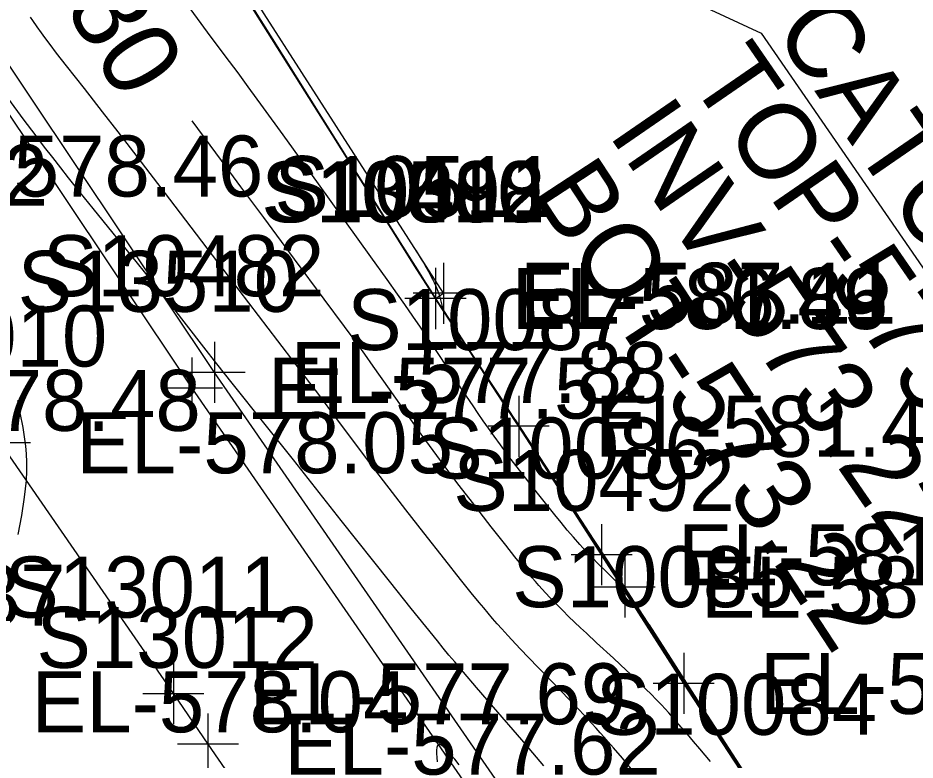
# Model space of a CAD drawing. Extents: x 1729869 to 1735532, y 648588 to 653771.
# Drawn here: x 1731975.7 to 1732034.5, y 650943.7 to 650992.4 of the extents above; entities that cross this region are included whole.
import ezdxf

# ---------------------------------------------------------------- set-up
doc = ezdxf.new("R2010")
doc.units = 0
for name, color, linetype in [('SURVEY - CONTOURS - Index with Text', 7, 'Continuous'), ('SURVEY - CONTOURS - Intermediate with optional Text', 7, 'Continuous'), ('SURVEY - DRAINAGE - Storm Sewer Text', 7, 'Continuous'), ('SURVEY - DTM - Breaklines', 7, 'Continuous'), ('SURVEY - DTM - Breaklines - Points - Elevations', 7, 'Continuous'), ('SURVEY - DTM - Breaklines - Points - Locators', 7, 'Continuous'), ('SURVEY - DTM - Breaklines - Points - Numbers', 7, 'Continuous'), ('SURVEY - MISCELLANEOUS - Bottom of MH and CB', 7, 'Continuous'), ('SURVEY - ROADSIDE BARRIERS - Points - Elevations', 7, 'Continuous'), ('SURVEY - ROADSIDE BARRIERS - Points - Locators', 7, 'Continuous'), ('SURVEY - ROADSIDE BARRIERS - Points - Numbers', 7, 'Continuous'), ('SURVEY - ROADSIDE BARRIERS with Text', 7, 'Continuous'), ('SURVEY - TRAFFIC CONTROL - Pavement Marking - Points - Elevations', 7, 'Continuous'), ('SURVEY - TRAFFIC CONTROL - Pavement Marking - Points - Numbers', 7, 'Continuous'), ('SURVEY - TRANSPORTATION - Features', 7, 'Continuous'), ('SURVEY - TRANSPORTATION - Features - Points - Elevations', 7, 'Continuous'), ('SURVEY - TRANSPORTATION - Features - Points - Locators', 7, 'Continuous'), ('SURVEY - TRANSPORTATION - Features - Points - Numbers', 7, 'Continuous'), ('SURVEY - TRANSPORTATION - Roads', 7, 'Continuous'), ('SURVEY - TRANSPORTATION - Roads - Points - Elevations', 7, 'Continuous'), ('SURVEY - TRANSPORTATION - Roads - Points - Locators', 7, 'Continuous'), ('SURVEY - TRANSPORTATION - Roads - Points - Numbers', 7, 'Continuous')]:
    doc.layers.add(name, color=color, linetype=linetype)

msp = doc.modelspace()

# ---------------------------------------------------------------- linework, layer by layer
at = {"layer": 'SURVEY - CONTOURS - Index with Text'}
for points in [[(1731990.106, 650994.569), (1731998.513, 650981.186), (1732002.185, 650975.342), (1732002.741, 650974.46), (1732003.04, 650973.985), (1732003.674, 650973.013), (1732005.357, 650970.432), (1732008.528, 650965.586), (1732010.41, 650962.695), (1732013.748, 650957.558), (1732014.896, 650955.782), (1732016.272, 650953.637), (1732017.448, 650951.8)], [(1732021.076, 650943.613), (1732020.374, 650944.448), (1732019.972, 650944.923), (1732019.566, 650945.397), (1732019.158, 650945.869), (1732018.749, 650946.335), (1732018.339, 650946.792), (1732017.857, 650947.317), (1732017.521, 650947.672), (1732017.183, 650948.02), (1732016.841, 650948.364), (1732016.425, 650948.772), (1732016.001, 650949.177), (1732015.574, 650949.58), (1732014.714, 650950.376), (1732013.615, 650951.392), (1732012.947, 650952.015), (1732012.555, 650952.384), (1732012.163, 650952.755), (1732011.775, 650953.128), (1732011.393, 650953.502), (1732011.018, 650953.877), (1732010.572, 650954.337), (1732010.264, 650954.668), (1732010.039, 650954.914), (1732009.819, 650955.161), (1732009.601, 650955.41), (1732009.385, 650955.661), (1732009.171, 650955.915), (1732008.865, 650956.283), (1732008.56, 650956.657), (1732008.257, 650957.034), (1732007.654, 650957.794), (1732006.706, 650959.006), (1732005.478, 650960.585), (1732004.613, 650961.706), (1732003.988, 650962.526), (1732003.559, 650963.098), (1732003.133, 650963.672), (1732002.655, 650964.329), (1732002.122, 650965.074), (1732000.037, 650968.023), (1731998.972, 650969.535), (1731998.416, 650970.316), (1731997.976, 650970.923), (1731997.093, 650972.126), (1731995.758, 650973.935), (1731993.813, 650976.554), (1731991.792, 650979.287), (1731990.304, 650981.299), (1731989.037, 650983.012), (1731987.096, 650985.62)], [(1732017.052, 650952.571), (1732020.203, 650947.655), (1732023.156, 650943.062)]]:
    msp.add_lwpolyline(points, dxfattribs=at)
at = {"layer": 'SURVEY - CONTOURS - Intermediate with optional Text'}
for points in [[(1731989.084, 650996.186), (1731998.643, 650980.975), (1732002.18, 650975.348), (1732002.821, 650974.33), (1732003.042, 650973.979), (1732003.573, 650973.166), (1732005.618, 650970.028), (1732008.097, 650966.237), (1732009.68, 650963.806), (1732013.378, 650958.105), (1732014.575, 650956.253), (1732015.794, 650954.353), (1732018.615, 650949.944), (1732019.823, 650948.068), (1732021.324, 650945.754), (1732025.088, 650939.975)], [(1732024.432, 650940.948), (1732021.077, 650946.081), (1732019.818, 650948.016), (1732019.004, 650949.276), (1732017.755, 650951.222), (1732014.969, 650955.582), (1732013.54, 650957.806), (1732011.123, 650961.548), (1732008.758, 650965.2), (1732007.097, 650967.75), (1732004.464, 650971.784), (1732003.509, 650973.256), (1732003.143, 650973.819), (1732003.047, 650973.966), (1732002.653, 650974.591), (1732001.84, 650975.875), (1732000.154, 650978.558), (1731996.288, 650984.713), (1731989.383, 650995.69)], [(1731990.681, 650993.634), (1731998.408, 650981.344), (1732002.414, 650974.971), (1732002.903, 650974.198), (1732003.045, 650973.971), (1732003.478, 650973.309), (1732003.897, 650972.662), (1732005.79, 650969.759), (1732008.134, 650966.17), (1732009.607, 650963.904), (1732013.159, 650958.421), (1732014.461, 650956.401), (1732015.852, 650954.231), (1732018.371, 650950.292), (1732019.449, 650948.616), (1732020.487, 650947.013), (1732023.192, 650942.863)], [(1732023.075, 650942.993), (1732021.446, 650945.479), (1732020.718, 650946.598), (1732020.355, 650947.16), (1732019.601, 650948.335), (1732019.313, 650948.782), (1732015.654, 650954.504), (1732015.45, 650954.799), (1732015.181, 650955.106), (1732014.899, 650955.407), (1732014.605, 650955.704), (1732014.304, 650956.001), (1732013.657, 650956.635), (1732013.4, 650956.894), (1732013.108, 650957.196), (1732012.913, 650957.403), (1732012.508, 650957.846), (1732012.1, 650958.309), (1732011.691, 650958.787), (1732011.281, 650959.277), (1732010.873, 650959.775), (1732010.344, 650960.431), (1732009.729, 650961.203), (1732009.336, 650961.703), (1732008.944, 650962.204), (1732008.555, 650962.706), (1732008.173, 650963.207), (1732007.798, 650963.703), (1732007.303, 650964.371), (1732006.895, 650964.933), (1732006.52, 650965.461), (1732006.184, 650965.941), (1732005.85, 650966.429), (1732005.516, 650966.92), (1732004.85, 650967.913), (1732003.091, 650970.556), (1732002.406, 650971.579), (1732002.063, 650972.086), (1732001.563, 650972.817), (1732001.041, 650973.567), (1732000.568, 650974.242), (1731999.875, 650975.219), (1731998.808, 650976.708), (1731995.375, 650981.484), (1731993.064, 650984.699), (1731991.789, 650986.463), (1731990.784, 650987.843), (1731990.114, 650988.754), (1731989.278, 650989.879), (1731988.115, 650991.435), (1731987.462, 650992.318), (1731986.977, 650992.985)], [(1731990.855, 650993.383), (1731992.233, 650991.196), (1731999.955, 650978.894), (1732001.982, 650975.668), (1732002.306, 650975.156), (1732003.039, 650973.988), (1732003.615, 650973.109), (1732005.261, 650970.585), (1732008.841, 650965.116), (1732011.841, 650960.514), (1732014.23, 650956.84), (1732015.338, 650955.125), (1732016.869, 650952.735), (1732019.022, 650949.373), (1732020.391, 650947.248), (1732023.069, 650943.115)], [(1732015.88, 650943.139), (1732015.303, 650943.821), (1732014.723, 650944.499), (1732014.379, 650944.895), (1732014.113, 650945.198), (1732013.846, 650945.499), (1732013.578, 650945.799), (1732013.308, 650946.096), (1732013.035, 650946.392), (1732012.761, 650946.686), (1732012.463, 650947.001), (1732011.861, 650947.625), (1732010.649, 650948.87), (1732009.749, 650949.805), (1732008.603, 650951.001), (1732008.057, 650951.579), (1732007.786, 650951.871), (1732007.397, 650952.3), (1732007.096, 650952.639), (1732006.799, 650952.982), (1732006.503, 650953.328), (1732006.21, 650953.677), (1732005.92, 650954.028), (1732005.397, 650954.67), (1732004.7, 650955.54), (1732003.659, 650956.856), (1732002.291, 650958.596), (1732001.105, 650960.115), (1732000.226, 650961.25), (1731999.64, 650962.015), (1731999.139, 650962.677), (1731996.633, 650966.023), (1731995.338, 650967.757), (1731994.821, 650968.441), (1731993.918, 650969.621), (1731992.721, 650971.184), (1731990.186, 650974.504), (1731987.737, 650977.723), (1731985.645, 650980.472), (1731983.283, 650983.558), (1731982.247, 650984.901), (1731981.239, 650986.198), (1731980.04, 650987.728), (1731978.87, 650989.214), (1731978.542, 650989.635), (1731978.219, 650990.053), (1731977.788, 650990.619), (1731977.45, 650991.075), (1731977.227, 650991.382), (1731976.94, 650991.784), (1731976.652, 650992.2), (1731976.507, 650992.415)], [(1732010.162, 650943.333), (1732009.442, 650944.182), (1732008.719, 650945.024), (1732006.847, 650947.179), (1732005.737, 650948.467), (1732004.879, 650949.469), (1732004.31, 650950.142), (1732003.934, 650950.592), (1732003.555, 650951.051), (1732003.174, 650951.517), (1732002.413, 650952.456), (1732001.457, 650953.648), (1732000.028, 650955.442), (1731996.874, 650959.422), (1731993.744, 650963.381), (1731991.892, 650965.712), (1731989.735, 650968.417), (1731988.731, 650969.688), (1731987.879, 650970.775), (1731985.742, 650973.515), (1731985.019, 650974.433), (1731984.439, 650975.159), (1731983.531, 650976.284), (1731980.611, 650979.877), (1731979.774, 650980.914), (1731979.007, 650981.874), (1731978.49, 650982.529), (1731977.966, 650983.203), (1731977.43, 650983.899), (1731976.811, 650984.717), (1731976.104, 650985.664), (1731975.032, 650987.116)], [(1732001.792, 650977.102), (1732002.119, 650976.553), (1732002.278, 650976.281), (1732002.434, 650976.011), (1732002.584, 650975.744), (1732002.728, 650975.481), (1732002.852, 650975.245), (1732002.967, 650975.012), (1732003.074, 650974.785), (1732003.168, 650974.564), (1732003.251, 650974.349), (1732003.319, 650974.141), (1732003.565, 650973.186), (1732005.852, 650969.689), (1732007.264, 650967.532), (1732008.58, 650965.518), (1732009.766, 650963.72), (1732011.373, 650961.259), (1732014.557, 650956.362), (1732015.655, 650954.661), (1732017.373, 650951.978), (1732019.237, 650949.069), (1732020.654, 650946.868), (1732023.327, 650942.738)], [(1731975.648, 650967.271), (1731975.883, 650966.139), (1731975.943, 650965.833), (1731976.002, 650965.52), (1731976.057, 650965.2), (1731976.126, 650964.75), (1731976.184, 650964.277), (1731976.227, 650963.774), (1731976.25, 650963.237), (1731976.249, 650962.662), (1731976.218, 650962.041), (1731976.102, 650960.937), (1731975.915, 650959.739), (1731975.676, 650958.485)], [(1732008.27, 650966.009), (1732012.614, 650959.368), (1732014.354, 650956.7), (1732015.366, 650955.139), (1732016.393, 650953.542), (1732019.226, 650949.118), (1732020.876, 650946.552), (1732023.542, 650942.425)], [(1732012.975, 650958.833), (1732014.743, 650956.125), (1732015.752, 650954.569), (1732016.964, 650952.684), (1732019.526, 650948.681), (1732021.348, 650945.847), (1732024.638, 650940.745)], [(1732020.428, 650947.332), (1732024.562, 650940.894)], [(1732004.606, 650943.398), (1732004.311, 650943.762), (1732004.067, 650944.054), (1732003.915, 650944.228), (1732003.843, 650944.308), (1732003.709, 650944.449), (1732003.586, 650944.566), (1732003.475, 650944.656), (1732003.378, 650944.714), (1732003.296, 650944.738), (1732003.23, 650944.722), (1732003.175, 650944.65), (1732003.141, 650944.524), (1732003.126, 650944.349), (1732003.128, 650944.13), (1732003.143, 650943.873), (1732003.17, 650943.584)]]:
    msp.add_lwpolyline(points, dxfattribs=at)
at = {"layer": 'SURVEY - DRAINAGE - Storm Sewer Text'}
msp.add_lwpolyline([(1731974.582, 651014.491), (1732024.407, 650991.366), (1732055.922, 650945.63)], dxfattribs=at)
at = {"layer": 'SURVEY - DTM - Breaklines'}
for points in [[(1732003.052, 650973.968), (1732003.581, 650974.31), (1731989.555, 650996.2), (1731978.607, 651014.105), (1731965.163, 651035.183), (1731951.942, 651056.407), (1731938.343, 651077.385), (1731924.593, 651098.267), (1731910.737, 651119.08), (1731897.035, 651139.992), (1731883.266, 651160.86), (1731869.448, 651181.699), (1731855.766, 651202.623), (1731841.938, 651223.455), (1731828.188, 651244.335), (1731813.142, 651266.45), (1731799.479, 651287.546), (1731797.002, 651291.324), (1731796.491, 651290.994), (1731796.236, 651290.836)], [(1732113.007, 650812.16), (1732098.885, 650832.683), (1732084.634, 650853.212), (1732070.443, 650873.845), (1732055.723, 650894.054), (1732042.075, 650914.908), (1732029.016, 650934.005), (1732015.459, 650955.044), (1732003.052, 650973.968), (1731989.798, 650995.07), (1731976.605, 651016.091), (1731963.895, 651036.118), (1731950.601, 651057.29), (1731936.956, 651078.167), (1731923.152, 651099.071)], [(1732102.153, 650804.616), (1732073.748, 650845.695), (1732045.347, 650886.865), (1732016.99, 650927.983), (1731988.568, 650969.12), (1731970.42, 650996.284), (1731969.494, 650997.549)], [(1732112.277, 650811.653), (1732107.544, 650817.969), (1732106.693, 650820.85), (1732101.431, 650827.09), (1732092.964, 650839.561), (1732080.137, 650858.446), (1732079.028, 650860.985), (1732076.136, 650864.318), (1732073.466, 650867.37), (1732053.717, 650896.357), (1732047.019, 650907.102), (1732041.081, 650915.154), (1732035.472, 650923.431), (1732030.287, 650932), (1732024.797, 650940.36), (1732019.321, 650948.729), (1732013.942, 650957.165), (1732008.505, 650965.587), (1732003.045, 650973.966)]]:
    msp.add_lwpolyline(points, dxfattribs=at)
at = {"layer": 'SURVEY - DTM - Breaklines - Points - Locators'}
for p, q in [((1732003.045, 650975.966), (1732003.045, 650971.966)), ((1732003.052, 650975.968), (1732003.052, 650971.968)), ((1732003.052, 650975.968), (1732003.052, 650971.968)), ((1732003.581, 650976.31), (1732003.581, 650972.31)), ((1732005.581, 650974.31), (1732001.581, 650974.31)), ((1732005.045, 650973.966), (1732001.045, 650973.966)), ((1732005.052, 650973.968), (1732001.052, 650973.968)), ((1732005.052, 650973.968), (1732001.052, 650973.968)), ((1731988.568, 650971.12), (1731988.568, 650967.12)), ((1731990.568, 650969.12), (1731986.568, 650969.12)), ((1732008.505, 650967.587), (1732008.505, 650963.587)), ((1732010.505, 650965.587), (1732006.505, 650965.587)), ((1732013.942, 650959.165), (1732013.942, 650955.165)), ((1732015.942, 650957.165), (1732011.942, 650957.165)), ((1732015.459, 650957.044), (1732015.459, 650953.044)), ((1732017.459, 650955.044), (1732013.459, 650955.044)), ((1732019.321, 650950.729), (1732019.321, 650946.729)), ((1732021.321, 650948.729), (1732017.321, 650948.729))]:
    msp.add_line(p, q, dxfattribs=at)
at = {"layer": 'SURVEY - ROADSIDE BARRIERS - Points - Locators'}
for p, q in [((1732003.045, 650975.966), (1732003.045, 650971.966)), ((1732003.045, 650975.966), (1732003.045, 650971.966)), ((1732005.045, 650973.966), (1732001.045, 650973.966)), ((1732005.045, 650973.966), (1732001.045, 650973.966))]:
    msp.add_line(p, q, dxfattribs=at)
at = {"layer": 'SURVEY - ROADSIDE BARRIERS with Text'}
msp.add_lwpolyline([(1732003.045, 650973.966), (1731988.236, 650997.512), (1731985.958, 651001.172), (1731980.623, 651009.635), (1731978.235, 651013.364), (1731975.843, 651017.144), (1731972.561, 651022.261), (1731967.185, 651030.692), (1731963.964, 651035.947), (1731958.619, 651044.399), (1731947.921, 651061.362), (1731942.452, 651069.66), (1731928.639, 651090.556), (1731914.818, 651111.43), (1731900.526, 651133.036), (1731886.679, 651153.809), (1731872.913, 651174.694), (1731859.053, 651195.599), (1731845.3, 651216.428), (1731831.509, 651237.32), (1731817.644, 651258.224), (1731811.485, 651267.57), (1731801.259, 651282.765), (1731796.236, 651290.836)], dxfattribs=at)
msp.add_lwpolyline([(1732003.045, 650973.966), (1731988.236, 650997.512), (1731985.958, 651001.172), (1731980.623, 651009.635), (1731978.235, 651013.364), (1731975.843, 651017.144), (1731972.561, 651022.261), (1731967.185, 651030.692), (1731963.964, 651035.947), (1731958.619, 651044.399), (1731947.921, 651061.362), (1731942.452, 651069.66), (1731928.639, 651090.556), (1731914.818, 651111.43), (1731900.526, 651133.036), (1731886.679, 651153.809), (1731872.913, 651174.694), (1731859.053, 651195.599), (1731845.3, 651216.428), (1731831.509, 651237.32), (1731817.644, 651258.224), (1731811.485, 651267.57), (1731801.259, 651282.765), (1731796.236, 651290.836)], dxfattribs=at)
at = {"layer": 'SURVEY - TRANSPORTATION - Features'}
msp.add_lwpolyline([(1731968.374, 650998.805), (1731968.232, 650997.903), (1731968.308, 650996.747), (1731968.923, 650995.273), (1731987.082, 650968.094), (1732015.503, 650926.959), (1732043.863, 650885.836), (1732072.262, 650844.669), (1732100.659, 650803.577)], dxfattribs=at)
at = {"layer": 'SURVEY - TRANSPORTATION - Features - Points - Locators'}
for p, q in [((1731987.082, 650970.094), (1731987.082, 650966.094)), ((1731989.082, 650968.094), (1731985.082, 650968.094))]:
    msp.add_line(p, q, dxfattribs=at)
at = {"layer": 'SURVEY - TRANSPORTATION - Roads'}
msp.add_lwpolyline([(1731866.856, 651135.373), (1731893.09, 651092.809), (1731909.859, 651065.556), (1731920.319, 651048.509), (1731940.263, 651016.166), (1731949.77, 651000.883), (1731962.084, 650982.655), (1731974.516, 650964.508), (1731985.875, 650948.049), (1731988.138, 650944.751), (1732026.696, 650888.752), (1732054.033, 650849.307), (1732065.396, 650832.853), (1732083.577, 650806.529), (1732093.848, 650791.753), (1732098.884, 650784.51)], dxfattribs=at)
at = {"layer": 'SURVEY - TRANSPORTATION - Roads - Points - Locators'}
for p, q in [((1731976.516, 650964.508), (1731972.516, 650964.508)), ((1731985.875, 650950.049), (1731985.875, 650946.049)), ((1731987.875, 650948.049), (1731983.875, 650948.049)), ((1731988.138, 650946.751), (1731988.138, 650942.751)), ((1731990.138, 650944.751), (1731986.138, 650944.751))]:
    msp.add_line(p, q, dxfattribs=at)

# ---------------------------------------------------------------- texts
at = {"layer": 'SURVEY - CONTOURS - Index with Text'}
msp.add_text('580', height=5, rotation=300.99513, dxfattribs=at).set_placement((1731976.765, 650996.353))
at = {"layer": 'SURVEY - DRAINAGE - Storm Sewer Text'}
for s, p in [('CATCH BASIN', (1732025.123, 650991.57)), ('TOP-575.76', (1732019.603, 650988.351)), ('INV-573.22', (1732014.324, 650984.759))]:
    msp.add_text(s, height=5, rotation=304.56994, dxfattribs=at).set_placement(p)
at = {"layer": 'SURVEY - DTM - Breaklines - Points - Elevations'}
for s, p in [('EL-581.46', (1732008.045, 650971.966)), ('EL-586.89', (1732008.052, 650971.968)), ('EL-586.89', (1732008.052, 650971.968)), ('EL-587.11', (1732008.581, 650972.31)), ('EL-577.88', (1731993.568, 650967.12)), ('EL-581.45', (1732013.505, 650963.587)), ('EL-581.21', (1732018.942, 650955.165)), ('EL-589.53', (1732020.459, 650953.044)), ('EL-580.47', (1732024.321, 650946.729))]:
    msp.add_text(s, height=4, dxfattribs=at).set_placement(p)
at = {"layer": 'SURVEY - DTM - Breaklines - Points - Numbers'}
for s, p in [('S10510', (1731991.639, 650978.968)), ('S10088', (1731991.758, 650978.966)), ('S10493', (1731991.812, 650978.968)), ('S10511', (1731992.499, 650979.31)), ('S10482', (1731977.328, 650974.12)), ('S10087', (1731997.265, 650970.587)), ('S10086', (1732002.592, 650962.165)), ('S10492', (1732004.219, 650960.044)), ('S10085', (1732008.081, 650953.729)), ('S10084', (1732013.557, 650945.36))]:
    msp.add_text(s, height=4, dxfattribs=at).set_placement(p)
at = {"layer": 'SURVEY - MISCELLANEOUS - Bottom of MH and CB'}
msp.add_text('BOT-573.22', height=5, rotation=303.22074, dxfattribs=at).set_placement((1732009.257, 650980.926))
at = {"layer": 'SURVEY - ROADSIDE BARRIERS - Points - Elevations'}
msp.add_text('EL-581.46', height=4, dxfattribs=at).set_placement((1732008.045, 650971.966))
msp.add_text('EL-581.46', height=4, dxfattribs=at).set_placement((1732008.045, 650971.966))
at = {"layer": 'SURVEY - ROADSIDE BARRIERS - Points - Numbers'}
msp.add_text('S13302', height=4, dxfattribs=at).set_placement((1731991.805, 650978.966))
msp.add_text('S13302', height=4, dxfattribs=at).set_placement((1731991.805, 650978.966))
at = {"layer": 'SURVEY - TRAFFIC CONTROL - Pavement Marking - Points - Elevations'}
for s, p in [('EL-578.82', (1731952.969, 650980.065)), ('EL-578.48', (1731962.986, 650965.289)), ('EL-578.04', (1731976.594, 650945.525))]:
    msp.add_text(s, height=4, dxfattribs=at).set_placement(p)
at = {"layer": 'SURVEY - TRAFFIC CONTROL - Pavement Marking - Points - Numbers'}
msp.add_text('S11587', height=4, dxfattribs=at).set_placement((1731960.354, 650952.525))
at = {"layer": 'SURVEY - TRANSPORTATION - Features - Points - Elevations'}
msp.add_text('EL-577.52', height=4, dxfattribs=at).set_placement((1731992.082, 650966.094))
at = {"layer": 'SURVEY - TRANSPORTATION - Features - Points - Numbers'}
msp.add_text('S13510', height=4, dxfattribs=at).set_placement((1731975.669, 650973.094))
at = {"layer": 'SURVEY - TRANSPORTATION - Roads - Points - Elevations'}
for s, p in [('EL-578.46', (1731967.084, 650980.655)), ('EL-578.82', (1731952.969, 650980.065)), ('EL-578.82', (1731952.969, 650980.065)), ('EL-578.05', (1731979.516, 650962.508)), ('EL-577.69', (1731990.875, 650946.049)), ('EL-577.62', (1731993.138, 650942.751))]:
    msp.add_text(s, height=4, dxfattribs=at).set_placement(p)
at = {"layer": 'SURVEY - TRANSPORTATION - Roads - Points - Numbers'}
for s, p in [('S13010', (1731963.103, 650969.508)), ('S13011', (1731974.793, 650953.049)), ('S13012', (1731976.898, 650949.751))]:
    msp.add_text(s, height=4, dxfattribs=at).set_placement(p)

doc.saveas('drawing.dxf')
